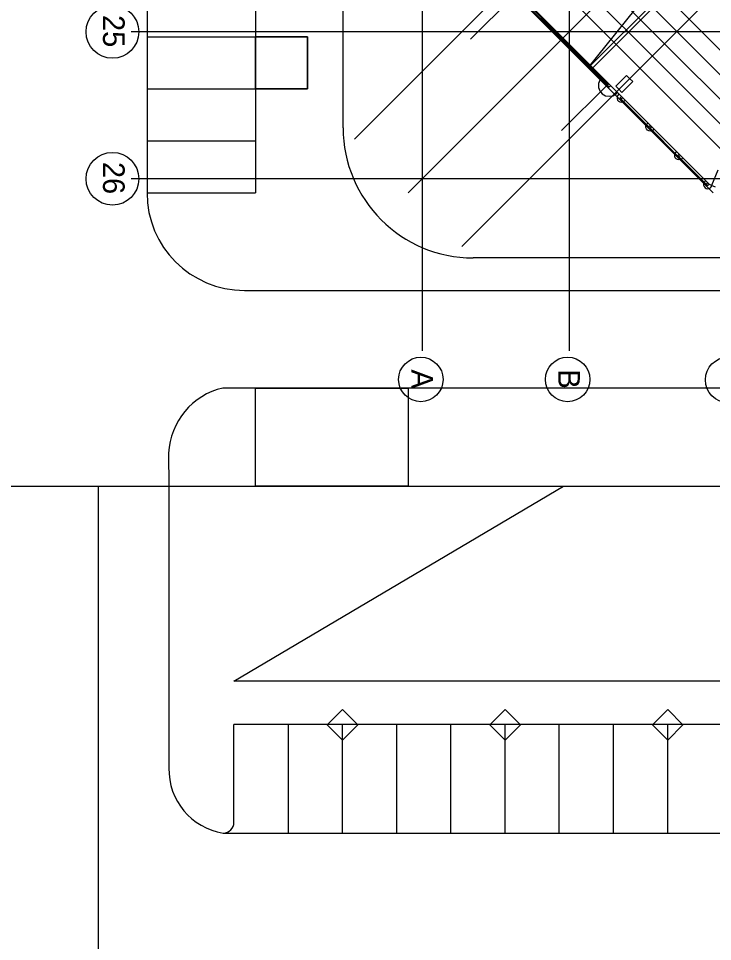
# Model space of a CAD drawing. Extents: x -264165 to -263575, y -1242333 to -1242036.
# Drawn here: x -263927.02 to -263895, y -1242275.99 to -1242233.41 of the extents above; entities that cross this region are included whole.
import ezdxf

# ---------------------------------------------------------------- set-up
doc = ezdxf.new("R2010")
doc.units = 0
doc.layers.add('KFA_HESCON_OSI_STAVBY', color=7, linetype='Continuous')
doc.layers.add('KFA_SITUACIA_DRS_VYTYCOVAK_SEDA', color=7, linetype='Continuous')

msp = doc.modelspace()

# ---------------------------------------------------------------- linework, layer by layer
at = {"layer": 'KFA_HESCON_OSI_STAVBY'}
for p, q in [((-263908.393, -1242080.447), (-263908.393, -1242248.737)), ((-263901.618, -1242080.447), (-263901.618, -1242248.737)), ((-263884.468, -1242216.882), (-263909.043, -1242241.457)), ((-263911.518, -1242238.982), (-263893.465, -1242220.93)), ((-263906.568, -1242243.932), (-263888.515, -1242225.879)), ((-263787.486, -1242234.032), (-263921.823, -1242234.032)), ((-263911.518, -1242238.982), (-263911.518, -1242238.982)), ((-263787.486, -1242240.807), (-263921.823, -1242240.807)), ((-263906.568, -1242243.932), (-263906.568, -1242243.932))]:
    msp.add_line(p, q, dxfattribs=at)
for centre, radius in [((-263922.688, -1242234.032), 1.216), ((-263922.688, -1242240.807), 1.216), ((-263908.458, -1242250.064), 1.027), ((-263901.683, -1242250.064), 1.027), ((-263894.283, -1242250.084), 1.047)]:
    msp.add_circle(centre, radius, dxfattribs=at)
at = {"layer": 'KFA_SITUACIA_DRS_VYTYCOVAK_SEDA'}
for p, q in [((-263921.093, -1242087.308), (-263921.093, -1242241.458)), ((-263916.093, -1242187.557), (-263916.093, -1242241.458)), ((-263900.731, -1242235.694), (-263890.255, -1242222.659)), ((-263894.968, -1242241.457), (-263909.043, -1242227.382)), ((-263912.043, -1242238.458), (-263912.043, -1242228.625)), ((-263901.033, -1242228.498), (-263896.083, -1242233.447)), ((-263901.033, -1242228.498), (-263896.083, -1242233.447)), ((-263896.649, -1242234.013), (-263901.599, -1242229.063)), ((-263896.649, -1242234.013), (-263901.599, -1242229.063)), ((-263902.164, -1242229.629), (-263897.215, -1242234.579)), ((-263902.164, -1242229.629), (-263897.215, -1242234.579)), ((-263902.73, -1242230.195), (-263897.78, -1242235.145)), ((-263902.73, -1242230.195), (-263897.78, -1242235.145)), ((-263898.346, -1242235.71), (-263903.296, -1242230.76)), ((-263898.346, -1242235.71), (-263903.296, -1242230.76)), ((-263900.731, -1242235.694), (-263895.982, -1242230.943)), ((-263900.629, -1242235.796), (-263895.875, -1242231.049)), ((-263904.374, -1242231.839), (-263899.424, -1242236.789)), ((-263904.374, -1242231.839), (-263899.424, -1242236.789)), ((-263904.074, -1242232.281), (-263906.17, -1242234.377)), ((-263904.074, -1242232.281), (-263906.17, -1242234.377)), ((-263901.977, -1242234.377), (-263904.074, -1242232.281)), ((-263901.977, -1242234.377), (-263904.074, -1242232.281)), ((-263904.059, -1242232.309), (-263902.002, -1242234.366)), ((-263904.059, -1242232.309), (-263902.002, -1242234.366)), ((-263901.995, -1242234.359), (-263904.052, -1242232.302)), ((-263901.995, -1242234.359), (-263904.052, -1242232.302)), ((-263904.031, -1242232.238), (-263901.935, -1242234.335)), ((-263904.031, -1242232.238), (-263901.935, -1242234.335)), ((-263899.778, -1242236.435), (-263904.021, -1242232.192)), ((-263899.778, -1242236.435), (-263904.021, -1242232.192)), ((-263903.391, -1242233.034), (-263900.629, -1242235.796)), ((-263903.281, -1242233.144), (-263900.731, -1242235.694)), ((-263903.277, -1242233.148), (-263900.731, -1242235.694)), ((-263896.083, -1242233.447), (-263892.949, -1242236.582)), ((-263896.083, -1242233.447), (-263892.949, -1242236.582)), ((-263893.28, -1242237.382), (-263896.649, -1242234.013)), ((-263893.28, -1242237.382), (-263896.649, -1242234.013)), ((-263921.093, -1242234.257), (-263916.093, -1242234.257)), ((-263913.693, -1242234.257), (-263916.093, -1242234.257)), ((-263916.093, -1242234.257), (-263916.093, -1242236.657)), ((-263916.093, -1242234.257), (-263913.693, -1242234.257)), ((-263916.093, -1242236.657), (-263916.093, -1242234.257)), ((-263913.693, -1242236.657), (-263913.693, -1242234.257)), ((-263913.693, -1242234.257), (-263913.693, -1242236.657)), ((-263902.002, -1242234.366), (-263901.995, -1242234.359)), ((-263902.002, -1242234.366), (-263901.995, -1242234.359)), ((-263901.952, -1242234.416), (-263902.002, -1242234.366)), ((-263901.952, -1242234.416), (-263902.002, -1242234.366)), ((-263901.995, -1242234.359), (-263901.945, -1242234.409)), ((-263901.995, -1242234.359), (-263901.945, -1242234.409)), ((-263901.977, -1242234.377), (-263901.935, -1242234.335)), ((-263901.977, -1242234.377), (-263901.935, -1242234.335)), ((-263901.92, -1242234.349), (-263901.963, -1242234.391)), ((-263901.92, -1242234.349), (-263901.963, -1242234.391)), ((-263899.866, -1242236.488), (-263901.963, -1242234.391)), ((-263899.866, -1242236.488), (-263901.963, -1242234.391)), ((-263901.945, -1242234.409), (-263901.952, -1242234.416)), ((-263901.945, -1242234.409), (-263901.952, -1242234.416)), ((-263901.952, -1242234.416), (-263899.895, -1242236.473)), ((-263901.952, -1242234.416), (-263899.895, -1242236.473)), ((-263899.888, -1242236.466), (-263901.945, -1242234.409)), ((-263899.888, -1242236.466), (-263901.945, -1242234.409)), ((-263901.92, -1242234.349), (-263899.824, -1242236.446)), ((-263901.92, -1242234.349), (-263899.824, -1242236.446)), ((-263897.215, -1242234.579), (-263893.611, -1242238.182)), ((-263897.215, -1242234.579), (-263893.611, -1242238.182)), ((-263897.78, -1242235.145), (-263893.943, -1242238.982)), ((-263897.78, -1242235.145), (-263893.943, -1242238.982)), ((-263894.274, -1242239.782), (-263898.346, -1242235.71)), ((-263894.274, -1242239.782), (-263898.346, -1242235.71)), ((-263900.197, -1242236.256), (-263900.256, -1242236.419)), ((-263900.197, -1242236.256), (-263900.256, -1242236.419)), ((-263900.158, -1242236.21), (-263900.197, -1242236.256)), ((-263900.158, -1242236.21), (-263900.197, -1242236.256)), ((-263900.087, -1242236.125), (-263900.113, -1242236.156)), ((-263900.087, -1242236.125), (-263900.113, -1242236.156)), ((-263898.965, -1242236.046), (-263899.46, -1242236.541)), ((-263898.965, -1242236.046), (-263899.46, -1242236.541)), ((-263898.823, -1242236.187), (-263898.965, -1242236.046)), ((-263898.823, -1242236.187), (-263898.965, -1242236.046)), ((-263898.682, -1242236.329), (-263898.823, -1242236.187)), ((-263898.682, -1242236.329), (-263898.823, -1242236.187)), ((-263921.093, -1242236.657), (-263916.093, -1242236.657)), ((-263916.093, -1242236.657), (-263913.693, -1242236.657)), ((-263913.693, -1242236.657), (-263916.093, -1242236.657)), ((-263899.866, -1242236.488), (-263901.963, -1242238.585)), ((-263899.866, -1242236.488), (-263901.963, -1242238.585)), ((-263900.256, -1242236.419), (-263900.256, -1242236.593)), ((-263900.256, -1242236.419), (-263900.256, -1242236.593)), ((-263900.256, -1242236.593), (-263900.197, -1242236.756)), ((-263900.256, -1242236.593), (-263900.197, -1242236.756)), ((-263899.895, -1242236.473), (-263899.888, -1242236.466)), ((-263899.895, -1242236.473), (-263899.888, -1242236.466)), ((-263899.849, -1242236.506), (-263899.888, -1242236.466)), ((-263899.849, -1242236.506), (-263899.888, -1242236.466)), ((-263899.866, -1242236.488), (-263899.824, -1242236.446)), ((-263899.866, -1242236.488), (-263899.824, -1242236.446)), ((-263899.849, -1242236.506), (-263899.778, -1242236.435)), ((-263899.849, -1242236.506), (-263899.778, -1242236.435)), ((-263899.764, -1242236.591), (-263899.849, -1242236.506)), ((-263899.764, -1242236.591), (-263899.849, -1242236.506)), ((-263899.693, -1242236.52), (-263899.764, -1242236.591)), ((-263899.693, -1242236.52), (-263899.764, -1242236.591)), ((-263899.636, -1242236.576), (-263899.693, -1242236.52)), ((-263899.636, -1242236.576), (-263899.693, -1242236.52)), ((-263899.637, -1242236.576), (-263899.212, -1242237.001)), ((-263899.637, -1242236.576), (-263899.212, -1242237.001)), ((-263899.46, -1242236.541), (-263899.318, -1242236.682)), ((-263899.46, -1242236.541), (-263899.318, -1242236.682)), ((-263899.46, -1242236.541), (-263899.318, -1242236.682)), ((-263899.46, -1242236.541), (-263899.318, -1242236.682)), ((-263899.318, -1242236.682), (-263899.177, -1242236.824)), ((-263899.318, -1242236.682), (-263899.177, -1242236.824)), ((-263899.318, -1242236.682), (-263899.177, -1242236.824)), ((-263899.318, -1242236.682), (-263899.177, -1242236.824)), ((-263899.177, -1242236.824), (-263898.682, -1242236.329)), ((-263899.177, -1242236.824), (-263898.682, -1242236.329)), ((-263900.197, -1242236.756), (-263900.085, -1242236.889)), ((-263900.197, -1242236.756), (-263900.085, -1242236.889)), ((-263900.085, -1242236.889), (-263899.935, -1242236.976)), ((-263900.085, -1242236.889), (-263899.935, -1242236.976)), ((-263899.935, -1242236.976), (-263899.764, -1242237.006)), ((-263899.935, -1242236.976), (-263899.764, -1242237.006)), ((-263899.764, -1242237.006), (-263899.593, -1242236.976)), ((-263899.764, -1242237.006), (-263899.593, -1242236.976)), ((-263899.593, -1242236.976), (-263899.442, -1242236.889)), ((-263899.593, -1242236.976), (-263899.442, -1242236.889)), ((-263899.442, -1242236.889), (-263899.388, -1242236.824)), ((-263899.442, -1242236.889), (-263899.388, -1242236.824)), ((-263895.135, -1242241.078), (-263899.424, -1242236.789)), ((-263895.135, -1242241.078), (-263899.424, -1242236.789)), ((-263899.424, -1242236.789), (-263895.135, -1242241.078)), ((-263899.424, -1242236.789), (-263895.135, -1242241.078)), ((-263899.378, -1242236.978), (-263899.402, -1242237.044)), ((-263899.378, -1242236.978), (-263899.402, -1242237.044)), ((-263899.402, -1242237.044), (-263899.402, -1242237.113)), ((-263899.402, -1242237.044), (-263899.402, -1242237.113)), ((-263899.402, -1242237.113), (-263899.378, -1242237.178)), ((-263899.402, -1242237.113), (-263899.378, -1242237.178)), ((-263899.334, -1242236.925), (-263899.378, -1242236.978)), ((-263899.334, -1242236.925), (-263899.378, -1242236.978)), ((-263899.305, -1242236.908), (-263899.334, -1242236.925)), ((-263899.305, -1242236.908), (-263899.334, -1242236.925)), ((-263899.269, -1242237.086), (-263899.198, -1242237.015)), ((-263899.269, -1242237.086), (-263899.198, -1242237.015)), ((-263899.233, -1242237.121), (-263899.269, -1242237.086)), ((-263899.233, -1242237.121), (-263899.269, -1242237.086)), ((-263899.233, -1242237.121), (-263899.24, -1242237.128)), ((-263899.233, -1242237.121), (-263899.24, -1242237.128)), ((-263897.926, -1242238.443), (-263899.24, -1242237.128)), ((-263897.926, -1242238.443), (-263899.24, -1242237.128)), ((-263899.142, -1242237.071), (-263899.212, -1242237.142)), ((-263899.142, -1242237.071), (-263899.212, -1242237.142)), ((-263899.212, -1242237.142), (-263897.939, -1242238.415)), ((-263899.212, -1242237.142), (-263897.939, -1242238.415)), ((-263899.198, -1242237.015), (-263899.142, -1242237.071)), ((-263899.198, -1242237.015), (-263899.142, -1242237.071)), ((-263899.378, -1242237.178), (-263899.334, -1242237.232)), ((-263899.378, -1242237.178), (-263899.334, -1242237.232)), ((-263899.334, -1242237.232), (-263899.274, -1242237.266)), ((-263899.334, -1242237.232), (-263899.274, -1242237.266)), ((-263899.274, -1242237.266), (-263899.205, -1242237.278)), ((-263899.274, -1242237.266), (-263899.205, -1242237.278)), ((-263899.205, -1242237.278), (-263899.137, -1242237.266)), ((-263899.205, -1242237.278), (-263899.137, -1242237.266)), ((-263899.137, -1242237.266), (-263899.115, -1242237.254)), ((-263899.137, -1242237.266), (-263899.115, -1242237.254)), ((-263899.106, -1242237.249), (-263899.077, -1242237.232)), ((-263899.106, -1242237.249), (-263899.077, -1242237.232)), ((-263899.077, -1242237.232), (-263899.033, -1242237.18)), ((-263899.077, -1242237.232), (-263899.033, -1242237.18)), ((-263898.073, -1242238.373), (-263898.052, -1242238.316)), ((-263898.073, -1242238.373), (-263898.052, -1242238.316)), ((-263898.073, -1242238.443), (-263898.073, -1242238.373)), ((-263898.073, -1242238.443), (-263898.073, -1242238.373)), ((-263898.048, -1242238.307), (-263898.004, -1242238.255)), ((-263898.048, -1242238.307), (-263898.004, -1242238.255)), ((-263898.004, -1242238.255), (-263897.975, -1242238.238)), ((-263898.004, -1242238.255), (-263897.975, -1242238.238)), ((-263897.939, -1242238.415), (-263897.869, -1242238.344)), ((-263897.939, -1242238.415), (-263897.869, -1242238.344)), ((-263897.919, -1242238.436), (-263897.926, -1242238.443)), ((-263897.919, -1242238.436), (-263897.926, -1242238.443)), ((-263897.904, -1242238.451), (-263897.919, -1242238.436)), ((-263897.904, -1242238.451), (-263897.919, -1242238.436)), ((-263897.812, -1242238.401), (-263897.883, -1242238.472)), ((-263897.812, -1242238.401), (-263897.883, -1242238.472)), ((-263897.869, -1242238.344), (-263897.812, -1242238.401)), ((-263897.869, -1242238.344), (-263897.812, -1242238.401)), ((-263898.049, -1242238.508), (-263898.073, -1242238.443)), ((-263898.049, -1242238.508), (-263898.073, -1242238.443)), ((-263898.004, -1242238.561), (-263898.049, -1242238.508)), ((-263898.004, -1242238.561), (-263898.049, -1242238.508)), ((-263897.944, -1242238.596), (-263898.004, -1242238.561)), ((-263897.944, -1242238.596), (-263898.004, -1242238.561)), ((-263897.876, -1242238.608), (-263897.944, -1242238.596)), ((-263897.876, -1242238.608), (-263897.944, -1242238.596)), ((-263897.904, -1242238.451), (-263897.911, -1242238.458)), ((-263897.904, -1242238.451), (-263897.911, -1242238.458)), ((-263896.596, -1242239.772), (-263897.911, -1242238.458)), ((-263896.596, -1242239.772), (-263897.911, -1242238.458)), ((-263897.883, -1242238.472), (-263896.61, -1242239.744)), ((-263897.883, -1242238.472), (-263896.61, -1242239.744)), ((-263897.807, -1242238.596), (-263897.876, -1242238.608)), ((-263897.807, -1242238.596), (-263897.876, -1242238.608)), ((-263897.785, -1242238.583), (-263897.807, -1242238.596)), ((-263897.785, -1242238.583), (-263897.807, -1242238.596)), ((-263897.747, -1242238.561), (-263897.776, -1242238.578)), ((-263897.747, -1242238.561), (-263897.776, -1242238.578)), ((-263897.704, -1242238.509), (-263897.747, -1242238.561)), ((-263897.704, -1242238.509), (-263897.747, -1242238.561)), ((-263921.093, -1242239.057), (-263916.093, -1242239.057)), ((-263896.743, -1242239.703), (-263896.723, -1242239.646)), ((-263896.743, -1242239.703), (-263896.723, -1242239.646)), ((-263896.743, -1242239.772), (-263896.743, -1242239.703)), ((-263896.743, -1242239.772), (-263896.743, -1242239.703)), ((-263896.718, -1242239.636), (-263896.675, -1242239.584)), ((-263896.718, -1242239.636), (-263896.675, -1242239.584)), ((-263896.675, -1242239.584), (-263896.646, -1242239.567)), ((-263896.675, -1242239.584), (-263896.646, -1242239.567)), ((-263896.61, -1242239.744), (-263896.539, -1242239.674)), ((-263896.61, -1242239.744), (-263896.539, -1242239.674)), ((-263896.539, -1242239.674), (-263896.483, -1242239.73)), ((-263896.539, -1242239.674), (-263896.483, -1242239.73)), ((-263896.719, -1242239.837), (-263896.743, -1242239.772)), ((-263896.719, -1242239.837), (-263896.743, -1242239.772)), ((-263896.675, -1242239.891), (-263896.719, -1242239.837)), ((-263896.675, -1242239.891), (-263896.719, -1242239.837)), ((-263896.615, -1242239.925), (-263896.675, -1242239.891)), ((-263896.615, -1242239.925), (-263896.675, -1242239.891)), ((-263896.546, -1242239.937), (-263896.615, -1242239.925)), ((-263896.546, -1242239.937), (-263896.615, -1242239.925)), ((-263896.589, -1242239.765), (-263896.596, -1242239.772)), ((-263896.589, -1242239.765), (-263896.596, -1242239.772)), ((-263896.574, -1242239.78), (-263896.589, -1242239.765)), ((-263896.574, -1242239.78), (-263896.589, -1242239.765)), ((-263896.581, -1242239.787), (-263896.574, -1242239.78)), ((-263896.581, -1242239.787), (-263896.574, -1242239.78)), ((-263895.267, -1242241.102), (-263896.581, -1242239.787)), ((-263895.267, -1242241.102), (-263896.581, -1242239.787)), ((-263896.483, -1242239.73), (-263896.553, -1242239.801)), ((-263896.483, -1242239.73), (-263896.553, -1242239.801)), ((-263896.553, -1242239.801), (-263895.28, -1242241.074)), ((-263896.553, -1242239.801), (-263895.28, -1242241.074)), ((-263896.478, -1242239.925), (-263896.546, -1242239.937)), ((-263896.478, -1242239.925), (-263896.546, -1242239.937)), ((-263896.456, -1242239.913), (-263896.478, -1242239.925)), ((-263896.456, -1242239.913), (-263896.478, -1242239.925)), ((-263896.418, -1242239.891), (-263896.447, -1242239.907)), ((-263896.418, -1242239.891), (-263896.447, -1242239.907)), ((-263896.374, -1242239.839), (-263896.418, -1242239.891)), ((-263896.374, -1242239.839), (-263896.418, -1242239.891)), ((-263894.749, -1242240.407), (-263895.043, -1242241.116)), ((-263894.749, -1242240.407), (-263895.043, -1242241.116)), ((-263895.393, -1242240.975), (-263895.414, -1242241.032)), ((-263895.393, -1242240.975), (-263895.414, -1242241.032)), ((-263895.345, -1242240.914), (-263895.389, -1242240.966)), ((-263895.345, -1242240.914), (-263895.389, -1242240.966)), ((-263895.316, -1242240.897), (-263895.345, -1242240.914)), ((-263895.316, -1242240.897), (-263895.345, -1242240.914)), ((-263895.414, -1242241.032), (-263895.414, -1242241.102)), ((-263895.414, -1242241.032), (-263895.414, -1242241.102)), ((-263895.414, -1242241.102), (-263895.39, -1242241.167)), ((-263895.414, -1242241.102), (-263895.39, -1242241.167)), ((-263895.39, -1242241.167), (-263895.345, -1242241.22)), ((-263895.39, -1242241.167), (-263895.345, -1242241.22)), ((-263895.345, -1242241.22), (-263895.285, -1242241.255)), ((-263895.345, -1242241.22), (-263895.285, -1242241.255)), ((-263895.285, -1242241.255), (-263895.217, -1242241.267)), ((-263895.285, -1242241.255), (-263895.217, -1242241.267)), ((-263895.28, -1242241.074), (-263895.21, -1242241.003)), ((-263895.28, -1242241.074), (-263895.21, -1242241.003)), ((-263895.267, -1242241.102), (-263895.26, -1242241.095)), ((-263895.267, -1242241.102), (-263895.26, -1242241.095)), ((-263895.224, -1242241.131), (-263895.26, -1242241.095)), ((-263895.224, -1242241.131), (-263895.26, -1242241.095)), ((-263895.153, -1242241.06), (-263895.224, -1242241.131)), ((-263895.153, -1242241.06), (-263895.224, -1242241.131)), ((-263895.217, -1242241.267), (-263895.148, -1242241.255)), ((-263895.217, -1242241.267), (-263895.148, -1242241.255)), ((-263895.21, -1242241.003), (-263895.153, -1242241.06)), ((-263895.21, -1242241.003), (-263895.153, -1242241.06)), ((-263895.148, -1242241.255), (-263895.088, -1242241.22)), ((-263895.148, -1242241.255), (-263895.088, -1242241.22)), ((-263895.043, -1242241.116), (-263895.135, -1242241.078)), ((-263895.043, -1242241.116), (-263895.135, -1242241.078)), ((-263895.088, -1242241.22), (-263895.044, -1242241.167)), ((-263895.088, -1242241.22), (-263895.044, -1242241.167)), ((-263895.044, -1242241.167), (-263895.027, -1242241.122)), ((-263895.044, -1242241.167), (-263895.027, -1242241.122)), ((-263894.858, -1242241.192), (-263895.043, -1242241.116)), ((-263894.858, -1242241.192), (-263895.043, -1242241.116)), ((-263921.093, -1242241.458), (-263916.093, -1242241.458)), ((-263896.21, -1242244.458), (-263906.043, -1242244.458)), ((-263851.968, -1242244.458), (-263896.21, -1242244.458)), ((-263916.593, -1242245.958), (-263896.71, -1242245.958)), ((-263896.71, -1242245.958), (-263808.225, -1242245.958)), ((-263807.725, -1242250.458), (-263917.593, -1242250.458)), ((-263916.093, -1242254.982), (-263916.093, -1242250.458)), ((-263916.093, -1242250.458), (-263909.043, -1242250.458)), ((-263916.093, -1242254.982), (-263916.093, -1242250.458)), ((-263916.093, -1242250.458), (-263909.043, -1242250.458)), ((-263909.043, -1242250.458), (-263909.043, -1242254.982)), ((-263909.043, -1242250.458), (-263909.043, -1242254.982)), ((-263920.098, -1242253.458), (-263920.08, -1242254.982)), ((-263970.068, -1242254.982), (-263802.068, -1242254.987)), ((-263929.58, -1242254.982), (-263920.08, -1242254.982)), ((-263923.33, -1242296.482), (-263923.33, -1242254.982)), ((-263920.08, -1242254.982), (-263920.08, -1242267.983)), ((-263920.08, -1242254.982), (-263901.868, -1242254.982)), ((-263917.08, -1242263.982), (-263901.868, -1242254.982)), ((-263917.08, -1242263.982), (-263901.868, -1242254.982)), ((-263909.043, -1242254.982), (-263916.093, -1242254.982)), ((-263909.043, -1242254.982), (-263916.093, -1242254.982)), ((-263901.868, -1242254.982), (-263854.468, -1242254.985)), ((-263901.868, -1242254.982), (-263854.468, -1242254.985)), ((-263854.468, -1242263.985), (-263917.08, -1242263.982)), ((-263854.468, -1242263.985), (-263917.08, -1242263.982)), ((-263912.775, -1242265.986), (-263912.068, -1242265.279)), ((-263912.068, -1242265.279), (-263911.361, -1242265.986)), ((-263905.275, -1242265.986), (-263904.568, -1242265.279)), ((-263904.568, -1242265.279), (-263903.861, -1242265.986)), ((-263897.775, -1242265.986), (-263897.068, -1242265.279)), ((-263897.775, -1242265.986), (-263897.068, -1242265.279)), ((-263897.068, -1242265.279), (-263896.361, -1242265.986)), ((-263897.068, -1242265.279), (-263896.361, -1242265.986)), ((-263807.068, -1242265.987), (-263917.08, -1242265.982)), ((-263917.08, -1242270.483), (-263917.08, -1242265.982)), ((-263914.568, -1242270.982), (-263914.568, -1242265.982)), ((-263912.068, -1242266.693), (-263912.775, -1242265.986)), ((-263912.068, -1242270.982), (-263912.068, -1242265.982)), ((-263911.361, -1242265.986), (-263912.068, -1242266.693)), ((-263909.568, -1242270.982), (-263909.568, -1242265.982)), ((-263907.068, -1242270.982), (-263907.068, -1242265.982)), ((-263904.568, -1242266.693), (-263905.275, -1242265.986)), ((-263904.568, -1242270.982), (-263904.568, -1242265.982)), ((-263903.861, -1242265.986), (-263904.568, -1242266.693)), ((-263902.068, -1242270.982), (-263902.068, -1242265.982)), ((-263899.568, -1242270.982), (-263899.568, -1242265.982)), ((-263897.068, -1242266.693), (-263897.775, -1242265.986)), ((-263897.068, -1242266.693), (-263897.775, -1242265.986)), ((-263897.068, -1242270.982), (-263897.068, -1242265.982)), ((-263896.361, -1242265.986), (-263897.068, -1242266.693)), ((-263896.361, -1242265.986), (-263897.068, -1242266.693)), ((-263917.578, -1242270.983), (-263807.068, -1242270.982))]:
    msp.add_line(p, q, dxfattribs=at)
for centre, radius, start, end in [((-263906.043, -1242238.458), 6, 180, 270), ((-263916.593, -1242241.458), 4.5, 180, 270), ((-263916.854, -1242253.621), 3.248, 103.1432, 177.1186), ((-263917.122, -1242268.058), 2.959, 178.5315, 261.1367), ((-263917.58, -1242270.483), 0.5, 270.2865, 0)]:
    msp.add_arc(centre, radius, start, end, dxfattribs=at)

# ---------------------------------------------------------------- texts
at = {"layer": 'KFA_HESCON_OSI_STAVBY'}
for s, p in [('25', (-263923.123, -1242233.255)), ('26', (-263923.123, -1242240.03)), ('A', (-263908.893, -1242249.599)), ('B', (-263902.118, -1242249.599))]:
    msp.add_text(s, height=1, rotation=270, dxfattribs=at).set_placement(p)

doc.saveas('drawing.dxf')
